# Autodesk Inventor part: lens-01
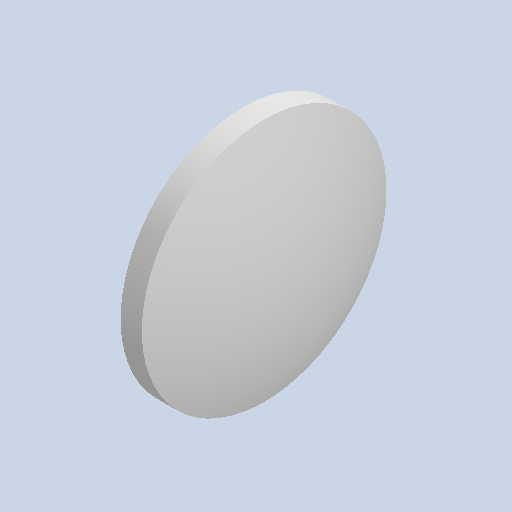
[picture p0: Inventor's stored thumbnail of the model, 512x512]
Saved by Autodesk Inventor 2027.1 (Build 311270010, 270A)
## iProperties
Created: 2026-07
Part Number: lens-01
Material: Generic
Document SubType Name: Modeling
Designer: dunge
Density: 1 g/cm^3
Appearance: Default
Author: dunge
SIDE_2_MINOR: 0.030 in
LENS_RADIUS: 0.750 in
SIDE_1_MAJOR: 0.300 in
SIDE_1_MINOR: 0.100 in
SIDE_2_MAJOR: 0.200 in
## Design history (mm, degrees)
derived "lens.ipt"
feature "Lens::lens.ipt"
tag "TaggingFeature1"
node "Lens"
other parameters: "SIDE_2_MINOR" = 0.762, "LENS_RADIUS" = 19.05, "SIDE_1_MINOR" = 2.54, "SIDE_1_MAJOR" = 7.62, "SIDE_2_MAJOR" = 5.08
